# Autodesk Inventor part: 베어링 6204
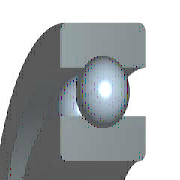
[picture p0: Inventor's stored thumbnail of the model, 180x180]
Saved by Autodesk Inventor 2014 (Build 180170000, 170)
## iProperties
Created: 2012-02
Part Number: 베어링 6204
Material: 강철, 연강
Description: 깊은 그루브 볼 베어링
Document SubType Name: Modeling
Standard: KS B 2023
Designer: mduedu
Standards Organization: KS
Language: ko-KR
Size Designation: 6204 - 20 x 47 x 14
Categories: <MemberInstance><Categories><Category DisplayName="샤프트 부품" InternalName="7f7aeb1f-a693-4053-b835-cee3144e0d98" Mnemonic="SHFT"><Category DisplayName="베어링" Inter
Density: 1 g/cm^3
Appearance: 노란색
IsCustomPart: 1
Author: mduedu
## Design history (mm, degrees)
sketch "스케치" dims "d0" = 7.02 (= -0.26 x WD + 0.26 x BD)
  geometry: L1 (3.49, 16.75)-(10.51, 16.75); L2 (7, 16.75)-(7, 13.24); L3 (7, 16.75)-(7, 20.26); L4 (4.392, 14.401)-(0, 14.401); L5 (0, 10)-(14, 10); L6 (4.392, 19.099)-(0, 19.099); L7 (0, 23.5)-(14, 23.5); L8 (14, 10)-(14, 14.401); L9 (9.608, 14.401)-(14, 14.401); L10 (9.608, 19.099)-(14, 19.099); L11 (14, 23.5)-(14, 19.099); L12 (-1.4, 0)-(8.4, 0) reference; L13 (0, -0.3)-(0, 5.3) reference
  constraints: 22 end point, 4 point on line, 2 collinear, 2 perpendicular, 2 symmetric about line, 1 midpoint, 1 parallel, 14 other
  dimensions: "d9" = 20 diameter of L5 L12 (= WD); "d11" = 47 diameter of L7 L12 (= BD); "d12" = 14 distance between parallel lines of L8 L13 (= KB); "d13" = 28.802 diameter of L9 L12 (= 0.326 x BD + 0.674 x WD)
revolve "본체" stored, may be unused: angle "d6" = 90 deg
revolve "볼" stored, may be unused: angle "d7" = 90 deg
pattern_circular "IDS_ARRAYBALL[SIMPL:T]" dims angle "d3" = 360 deg
body "Solid1"
fillet "모깎기1" dims "d1" = 1 (= KRS)
other parameters: "WD" = 20 [user parameter; used in 5 equation terms], "BD" = 47 [user parameter; used in 5 equation terms], "KB" = 14 [user parameter; used in 1 equation term], "KRS" = 1 [user parameter; used in 1 equation term], "d4" = 0, "d5" = 0, "d8" = 0, "d14" = 0, "d15" = 0, "BBA" = 0 [user parameter], "BC0" = 6550000 [user parameter], "BC" = 1.27e+07 [user parameter], "BR" = 23.5 (= 0.5 x BD) [user parameter]
